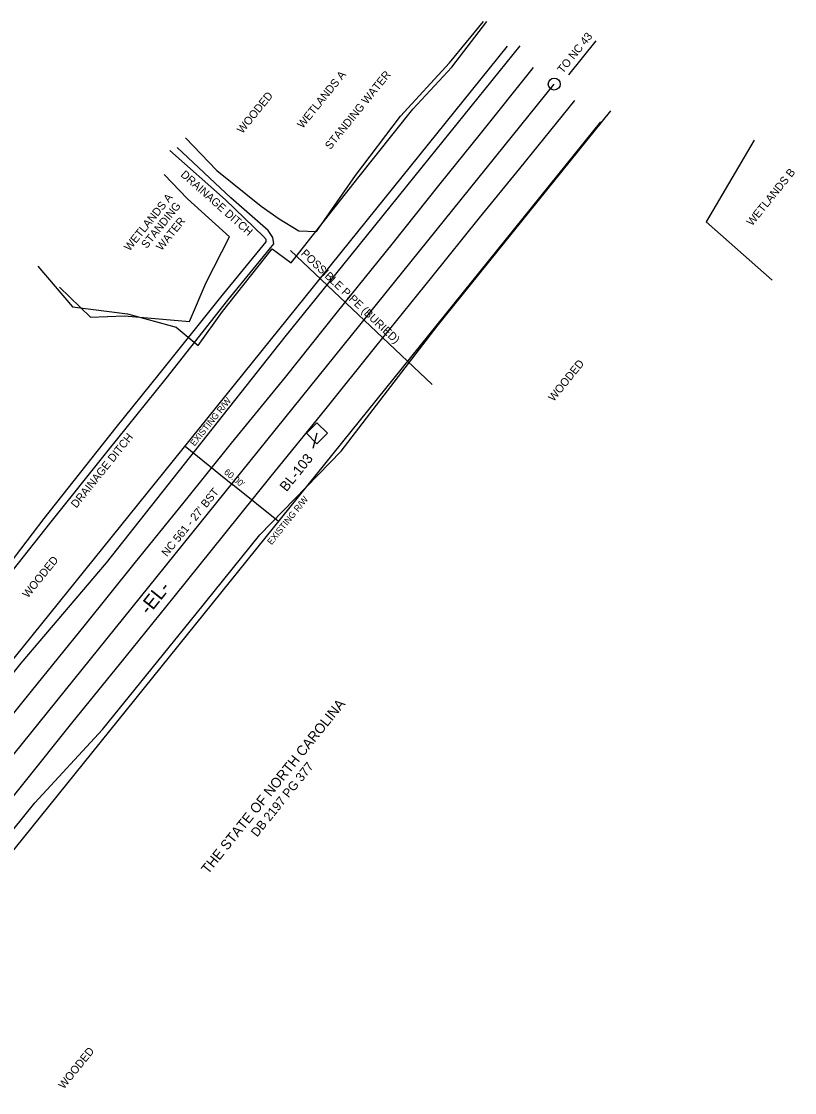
# Model space of a CAD drawing. Extents: x 2292498 to 2294521, y 891760 to 894087.
# Drawn here: x 2294026 to 2294413, y 893552 to 894087 of the extents above; entities that cross this region are included whole.
import ezdxf

# ---------------------------------------------------------------- set-up
doc = ezdxf.new("R2010")
doc.units = 0
for name, color, linetype in [('CTL Secondary Horizontal and Vertical CELL', 7, 'Continuous'), ('CTL Secondary Horizontal and Vertical Text', 7, 'Continuous'), ('Exist Environmental Wetland Boundary', 7, 'Continuous'), ('Exist Environmental Wetland Boundary Text', 7, 'Continuous'), ('Exist Horizontal Alignment', 7, 'Continuous'), ('Exist Horizontal Alignment Direction Label', 7, 'Continuous'), ('Exist Horizontal Alignment Point', 7, 'Continuous'), ('Exist Hydro Stream or Body of Water', 7, 'Continuous'), ('Exist Hydro Stream or Body of Water Text', 7, 'Continuous'), ('Exist Property Deed Book Text', 7, 'Continuous'), ('Exist Property Owner Text', 7, 'Continuous'), ('Exist Right of Way Line', 7, 'Continuous'), ('Exist Right of Way Line Text', 7, 'Continuous'), ('Exist Right of Way Width CELL', 7, 'Continuous'), ('Exist Roads EOP', 7, 'Continuous'), ('Exist Roads EOP Leader', 7, 'Continuous'), ('Exist Roads EOP Text', 7, 'Continuous'), ('Exist Structure Minor Storm Sewer Line', 7, 'Continuous'), ('Exist Structure Minor Storm Sewer Line Text', 7, 'Continuous'), ('Exist Vegetation Woods Line', 7, 'Continuous'), ('Exist Vegetation Woods Line Text', 7, 'Continuous')]:
    doc.layers.add(name, color=color, linetype=linetype)

msp = doc.modelspace()

# ---------------------------------------------------------------- linework, layer by layer
at = {"layer": 'CTL Secondary Horizontal and Vertical CELL'}
msp.add_line((2294174.05, 893881.57), (2294174.05, 893881.57), dxfattribs=at)
msp.add_lwpolyline([(2294168.83, 893881.58), (2294174.07, 893886.83), (2294179.32, 893881.58), (2294174.08, 893876.33)], close=True, dxfattribs=at)
at = {"layer": 'CTL Secondary Horizontal and Vertical Text'}
msp.add_line((2294174.05, 893881.57), (2294171.99, 893873.92), dxfattribs=at)
at = {"layer": 'Exist Environmental Wetland Boundary'}
for points in [[(2294034.46, 893965.09), (2294051.88, 893944.73), (2294079.33, 893941.24), (2294103.62, 893934.66), (2294114.67, 893925.36), (2294126.87, 893942.44), (2294151.6, 893973.8), (2294161.1, 893966.67), (2294194.47, 894009.04), (2294222.04, 894043.61), (2294241.54, 894064.52), (2294258.97, 894087.28)], [(2294392.66, 894027.99), (2294368.72, 893987.28), (2294401.69, 893958.11)]]:
    msp.add_lwpolyline(points, dxfattribs=at)
at = {"layer": 'Exist Horizontal Alignment'}
msp.add_line((2293668.45, 893282.57), (2294292.7, 894056.1), dxfattribs=at)
at = {"layer": 'Exist Horizontal Alignment Point'}
msp.add_circle((2294292.7, 894056.1), 3, dxfattribs=at)
at = {"layer": 'Exist Hydro Stream or Body of Water'}
for points in [[(2294108.26, 894029.28), (2294124.01, 894012.84), (2294146.22, 893995.1), (2294155.18, 893988.77), (2294165.05, 893982.81), (2294173.81, 893982.44), (2294193.31, 894010.47), (2294215.81, 894040.06), (2294240.4, 894066.63), (2294257.37, 894087.38)], [(2293968.14, 893745.05), (2293986.28, 893767.63), (2294022.34, 893813.58), (2294040.46, 893836.56), (2294069.7, 893872.94), (2294098.71, 893908.94), (2294129.49, 893948.14), (2294150.33, 893973.58), (2294152.51, 893976.22), (2294152.08, 893979.35), (2294149.75, 893982.98), (2294131.07, 893999.21), (2294104.21, 894024.33)], [(2293965.42, 893747.6), (2293983.52, 893770.46), (2294020.17, 893816.01), (2294037.74, 893838.96), (2294073.63, 893884.39), (2294095.2, 893911.15), (2294125.99, 893949.6), (2294148.73, 893977.27), (2294148.61, 893978.43), (2294147.33, 893979.83), (2294128.27, 893998.23), (2294100.51, 894022.9)], [(2294045.28, 893954.57), (2294060.89, 893939.6), (2294077.89, 893940.33), (2294110.41, 893937.36), (2294118.71, 893956.93), (2294130.37, 893979.74), (2294109.33, 893998.74), (2294097.69, 894010.96)]]:
    msp.add_lwpolyline(points, dxfattribs=at)
at = {"layer": 'Exist Right of Way Line'}
for p, q in [((2293645.1, 893301.41), (2294269.35, 894074.94)), ((2293691.79, 893263.73), (2294316.04, 894037.26))]:
    msp.add_line(p, q, dxfattribs=at)
at = {"layer": 'Exist Right of Way Width CELL'}
for p in [(2294108.11, 893875.14), (2294154.8, 893837.46)]:
    msp.add_line(p, (2294131.97, 893855.88), dxfattribs=at)
at = {"layer": 'Exist Roads EOP'}
for points in [[(2293935.28, 893633.81), (2293937.79, 893636.87), (2293961.83, 893666.23), (2293986.02, 893696.74), (2294007.23, 893722.82), (2294031.33, 893752.69), (2294058.41, 893786.02), (2294082.69, 893816.27), (2294107.66, 893847.21), (2294131.39, 893876.6), (2294158.26, 893909.62), (2294184.25, 893942.29), (2294211.73, 893976.1), (2294235.74, 894006.24), (2294255.79, 894031.21), (2294282.38, 894064.31)], [(2293955.11, 893617.9), (2293957.85, 893621.39), (2293982.73, 893650.99), (2294005.99, 893680.08), (2294027.69, 893706.97), (2294051.48, 893736.65), (2294078.15, 893769.54), (2294102.63, 893799.93), (2294128.01, 893831.31), (2294151.11, 893860.1), (2294178.02, 893893.21), (2294203.53, 893924.91), (2294231.5, 893959.53), (2294255.32, 893989.22), (2294275.52, 894013.95), (2294303.02, 894047.9)]]:
    msp.add_lwpolyline(points, dxfattribs=at)
at = {"layer": 'Exist Roads EOP Leader'}
msp.add_line((2294313.49, 894077.7), (2294299.89, 894060.77), dxfattribs=at)
at = {"layer": 'Exist Structure Minor Storm Sewer Line'}
msp.add_line((2294160.83, 893972.98), (2294231.64, 893905.94), dxfattribs=at)
at = {"layer": 'Exist Vegetation Woods Line'}
for points in [[(2294275.43, 894075.18), (2294226.51, 894014.61), (2294183.35, 893961.16), (2294158.03, 893929.81), (2294068.65, 893816.83), (2294026.01, 893766.63), (2293989.31, 893721.19), (2293939.84, 893666.63), (2293924.14, 893658.56), (2293910.07, 893654.4), (2293900.21, 893631.61), (2293889.51, 893637.85), (2293870.86, 893631.28), (2293841.9, 893663.23), (2293832.19, 893679.37), (2293820.24, 893686.32), (2293801.97, 893711.56), (2293781.32, 893743.5)], [(2294054.09, 893434.89), (2294014.85, 893475.1), (2293994.42, 893496.91), (2293989.72, 893508.14), (2293970.8, 893518.83), (2293959.99, 893531.71), (2293944.74, 893550.81), (2293937.07, 893564.86), (2293953.29, 893581.7), (2293971.02, 893590.11), (2293988.69, 893612), (2293976.08, 893629.18), (2294000.58, 893656.8), (2294032.96, 893696.89), (2294066.89, 893733.51), (2294113.65, 893791.41), (2294145.47, 893830.82), (2294186.13, 893872.69), (2294234.1, 893935.06), (2294280.63, 893992.69), (2294320.98, 894042.65)]]:
    msp.add_lwpolyline(points, dxfattribs=at)

# ---------------------------------------------------------------- texts
at = {"layer": 'CTL Secondary Horizontal and Vertical Text'}
msp.add_text('BL-103', height=5, rotation=51.0765, dxfattribs=at).set_placement((2294158.85, 893852.09))
at = {"layer": 'Exist Environmental Wetland Boundary Text'}
for s, p in [('WETLANDS A', (2294166.93, 894033.61)), ('WETLANDS B', (2294391.63, 893984.88)), ('WETLANDS A', (2294080.37, 893972.31))]:
    msp.add_text(s, height=4, rotation=51.0765, dxfattribs=at).set_placement(p)
at = {"layer": 'Exist Horizontal Alignment Direction Label'}
msp.add_text('-EL-', height=7, rotation=51.494, dxfattribs=at).set_placement((2294090.06, 893790.41))
at = {"layer": 'Exist Hydro Stream or Body of Water Text'}
for s, rotation, p in [('STANDING WATER', 51.0765, (2294180.8, 894023.05)), ('DRAINAGE DITCH', 318.3802, (2294105.59, 894010.36)), ('STANDING ', 51.0765, (2294088.92, 893973.61)), ('WATER', 51.0765, (2294096.4, 893972.52)), ('DRAINAGE DITCH', 51.2152, (2294053.77, 893843.9))]:
    msp.add_text(s, height=4, rotation=rotation, dxfattribs=at).set_placement(p)
at = {"layer": 'Exist Property Deed Book Text'}
msp.add_text('DB 2197 PG 377', height=4.5, rotation=51.0765, dxfattribs=at).set_placement((2294144.13, 893679.53))
at = {"layer": 'Exist Property Owner Text'}
msp.add_text('THE STATE OF NORTH CAROLINA', height=5, rotation=51.0765, dxfattribs=at).set_placement((2294119.63, 893660.95))
at = {"layer": 'Exist Right of Way Line Text'}
for p in [(2294112.86, 893874.87), (2294151.37, 893825.57)]:
    msp.add_text('EXISTING R/W', height=3.2, rotation=51.0961, dxfattribs=at).set_placement(p)
at = {"layer": 'Exist Right of Way Width CELL'}
msp.add_text("60.00'", height=3.2, rotation=321.0961, dxfattribs=at).set_placement((2294127.3, 893861.61))
at = {"layer": 'Exist Roads EOP Text'}
for s, rotation, p in [('TO NC 43', 51.2211, (2294296.96, 894061.1)), ("NC 561 - 27' BST", 51.0493, (2294099.06, 893819.66))]:
    msp.add_text(s, height=4, rotation=rotation, dxfattribs=at).set_placement(p)
at = {"layer": 'Exist Structure Minor Storm Sewer Line Text'}
msp.add_text('POSSIBLE PIPE (BURIED)', height=4, rotation=316.5663, dxfattribs=at).set_placement((2294165.74, 893971.02))
at = {"layer": 'Exist Vegetation Woods Line Text'}
for p in [(2294136.82, 894031.02), (2294292.42, 893897.18), (2294029.55, 893798.97), (2294047.49, 893553.61)]:
    msp.add_text('WOODED', height=4, rotation=51.0765, dxfattribs=at).set_placement(p)

doc.saveas('drawing.dxf')
